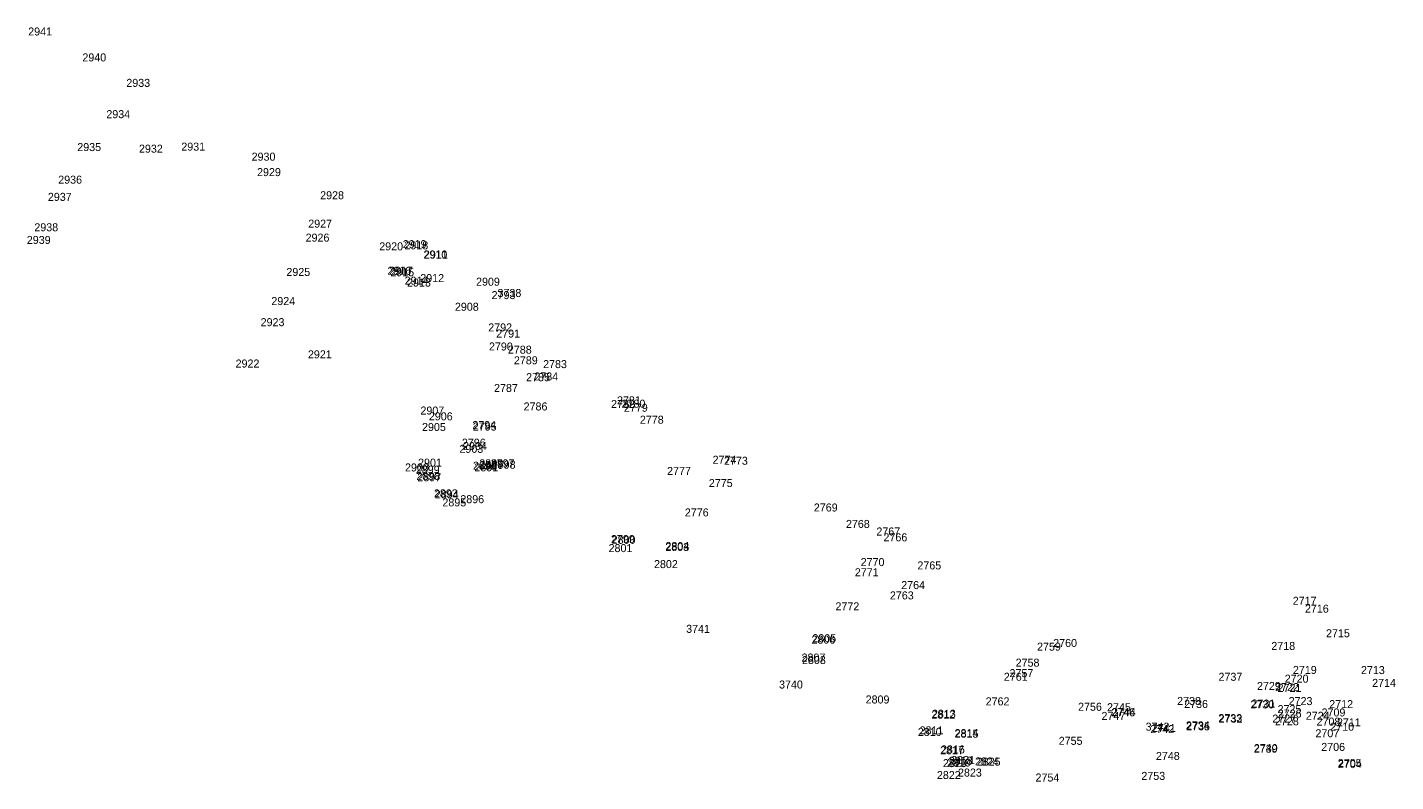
# Model space of a CAD drawing. Extents: x -740053 to -737517, y -1033516 to -1032476.
# Drawn here: x -738857.4 to -738763.4, y -1032625.6 to -1032573.7 of the extents above; entities that cross this region are included whole.
import ezdxf

# ---------------------------------------------------------------- set-up
doc = ezdxf.new("R2010")
doc.units = 0
doc.layers.add('bod-cislo', color=7, linetype='Continuous')

msp = doc.modelspace()

# ---------------------------------------------------------------- texts
at = {"layer": 'bod-cislo'}
for s, p in [('2941', (-738857.359, -1032574.293)), ('2940', (-738853.638, -1032576.073)), ('2933', (-738850.618, -1032577.823)), ('2934', (-738851.991, -1032579.973)), ('2935', (-738853.988, -1032582.233)), ('2932', (-738849.748, -1032582.343)), ('2931', (-738846.839, -1032582.203)), ('2930', (-738842.008, -1032582.893)), ('2929', (-738841.635, -1032583.953)), ('2936', (-738855.298, -1032584.473)), ('2937', (-738856.008, -1032585.653)), ('2928', (-738837.298, -1032585.543)), ('2938', (-738856.938, -1032587.743)), ('2927', (-738838.118, -1032587.493)), ('2939', (-738857.455, -1032588.613)), ('2926', (-738838.298, -1032588.453)), ('2919', (-738831.625, -1032588.903)), ('2920', (-738833.238, -1032589.053)), ('2918', (-738831.508, -1032588.983)), ('2910', (-738830.198, -1032589.613)), ('2911', (-738830.169, -1032589.623)), ('2925', (-738839.618, -1032590.813)), ('2916', (-738832.678, -1032590.733)), ('2917', (-738832.556, -1032590.729)), ('2915', (-738832.478, -1032590.833)), ('2914', (-738831.491, -1032591.413)), ('2913', (-738831.328, -1032591.543)), ('2912', (-738830.418, -1032591.233)), ('2909', (-738826.585, -1032591.483)), ('2793', (-738825.518, -1032592.403)), ('3738', (-738825.11, -1032592.256)), ('2924', (-738840.651, -1032592.813)), ('2908', (-738828.038, -1032593.203)), ('2923', (-738841.388, -1032594.263)), ('2792', (-738825.748, -1032594.623)), ('2791', (-738825.199, -1032595.043)), ('2921', (-738838.139, -1032596.473)), ('2790', (-738825.698, -1032595.933)), ('2788', (-738824.398, -1032596.153)), ('2922', (-738843.108, -1032597.103)), ('2789', (-738823.985, -1032596.883)), ('2783', (-738821.978, -1032597.143)), ('2785', (-738823.148, -1032598.043)), ('2784', (-738822.581, -1032597.993)), ('2787', (-738825.348, -1032598.783)), ('2786', (-738823.318, -1032600.053)), ('2782', (-738817.308, -1032599.883)), ('2781', (-738816.899, -1032599.633)), ('2780', (-738816.588, -1032599.863)), ('2779', (-738816.425, -1032600.143)), ('2907', (-738830.408, -1032600.333)), ('2906', (-738829.828, -1032600.733)), ('2778', (-738815.328, -1032600.963)), ('2905', (-738830.298, -1032601.463)), ('2794', (-738826.841, -1032601.333)), ('2795', (-738826.808, -1032601.433)), ('2903', (-738827.728, -1032602.963)), ('2796', (-738827.558, -1032602.543)), ('2904', (-738827.481, -1032602.773)), ('2901', (-738830.569, -1032603.913)), ('2889', (-738826.365, -1032603.963)), ('2797', (-738825.578, -1032603.963)), ('2774', (-738810.331, -1032603.713)), ('2773', (-738809.548, -1032603.783)), ('2900', (-738831.468, -1032604.243)), ('2899', (-738830.725, -1032604.393)), ('2898', (-738830.688, -1032604.833)), ('2897', (-738830.618, -1032604.913)), ('2892', (-738826.798, -1032604.123)), ('2891', (-738826.699, -1032604.233)), ('2890', (-738826.348, -1032604.073)), ('2798', (-738825.508, -1032604.053)), ('2777', (-738813.458, -1032604.483)), ('2775', (-738810.588, -1032605.313)), ('2893', (-738829.478, -1032606.023)), ('2894', (-738829.421, -1032606.093)), ('2895', (-738828.898, -1032606.643)), ('2896', (-738827.668, -1032606.423)), ('2776', (-738812.238, -1032607.333)), ('2769', (-738803.375, -1032606.993)), ('2768', (-738801.168, -1032608.123)), ('2767', (-738799.078, -1032608.643)), ('2799', (-738817.315, -1032609.163)), ('2800', (-738817.268, -1032609.213)), ('2804', (-738813.571, -1032609.643)), ('2766', (-738798.588, -1032609.043)), ('2801', (-738817.479, -1032609.783)), ('2803', (-738813.578, -1032609.703)), ('2802', (-738814.358, -1032610.883)), ('2771', (-738800.559, -1032611.443)), ('2770', (-738800.158, -1032610.743)), ('2765', (-738796.258, -1032610.973)), ('2764', (-738797.371, -1032612.323)), ('2763', (-738798.148, -1032613.033)), ('2717', (-738770.468, -1032613.403)), ('2772', (-738801.888, -1032613.783)), ('2716', (-738769.628, -1032613.943)), ('3741', (-738812.149, -1032615.33)), ('2806', (-738803.538, -1032616.073)), ('2805', (-738803.478, -1032615.973)), ('2715', (-738768.178, -1032615.633)), ('2759', (-738788.035, -1032616.553)), ('2760', (-738786.928, -1032616.303)), ('2718', (-738771.938, -1032616.503)), ('2807', (-738804.218, -1032617.303)), ('2808', (-738804.188, -1032617.473)), ('2758', (-738789.508, -1032617.653)), ('2761', (-738790.319, -1032618.623)), ('2757', (-738789.928, -1032618.373)), ('2737', (-738775.568, -1032618.623)), ('2720', (-738771.018, -1032618.753)), ('2719', (-738770.455, -1032618.153)), ('2713', (-738765.778, -1032618.163)), ('2714', (-738765.011, -1032619.043)), ('3740', (-738805.765, -1032619.154)), ('2729', (-738772.925, -1032619.253)), ('2722', (-738771.678, -1032619.333)), ('2721', (-738771.509, -1032619.383)), ('2809', (-738799.815, -1032620.183)), ('2762', (-738791.568, -1032620.313)), ('2756', (-738785.218, -1032620.683)), ('2745', (-738783.228, -1032620.713)), ('2738', (-738778.408, -1032620.283)), ('2736', (-738777.928, -1032620.493)), ('2730', (-738773.378, -1032620.523)), ('2731', (-738773.299, -1032620.463)), ('2725', (-738771.508, -1032620.843)), ('2723', (-738770.748, -1032620.293)), ('2712', (-738767.958, -1032620.503)), ('2812', (-738795.298, -1032621.223)), ('2813', (-738795.258, -1032621.163)), ('2747', (-738783.608, -1032621.313)), ('2746', (-738782.938, -1032621.063)), ('2744', (-738782.891, -1032621.043)), ('2733', (-738775.578, -1032621.463)), ('2732', (-738775.558, -1032621.503)), ('2727', (-738771.868, -1032621.493)), ('2728', (-738771.688, -1032621.683)), ('2726', (-738771.498, -1032621.153)), ('2724', (-738769.571, -1032621.303)), ('2708', (-738768.828, -1032621.703)), ('2709', (-738768.485, -1032621.073)), ('2711', (-738767.429, -1032621.753)), ('2810', (-738796.228, -1032622.413)), ('2811', (-738796.109, -1032622.303)), ('2814', (-738793.701, -1032622.493)), ('2815', (-738793.698, -1032622.533)), ('3742', (-738780.575, -1032622.052)), ('2742', (-738780.248, -1032622.213)), ('2741', (-738780.139, -1032622.143)), ('2734', (-738777.811, -1032621.963)), ('2735', (-738777.788, -1032622.023)), ('2707', (-738768.908, -1032622.503)), ('2710', (-738767.888, -1032622.053)), ('2817', (-738794.698, -1032623.673)), ('2816', (-738794.638, -1032623.613)), ('2755', (-738786.548, -1032623.023)), ('2739', (-738773.145, -1032623.563)), ('2740', (-738773.138, -1032623.523)), ('2706', (-738768.508, -1032623.443)), ('2820', (-738794.508, -1032624.553)), ('2819', (-738794.215, -1032624.513)), ('2818', (-738794.108, -1032624.393)), ('2821', (-738793.939, -1032624.343)), ('2824', (-738792.301, -1032624.443)), ('2825', (-738792.178, -1032624.453)), ('2748', (-738779.868, -1032624.063)), ('2705', (-738767.368, -1032624.543)), ('2704', (-738767.361, -1032624.623)), ('2822', (-738794.918, -1032625.373)), ('2823', (-738793.468, -1032625.203)), ('2754', (-738788.141, -1032625.543)), ('2753', (-738780.868, -1032625.433))]:
    msp.add_text(s, height=0.55, dxfattribs=at).set_placement(p)

doc.saveas('drawing.dxf')
